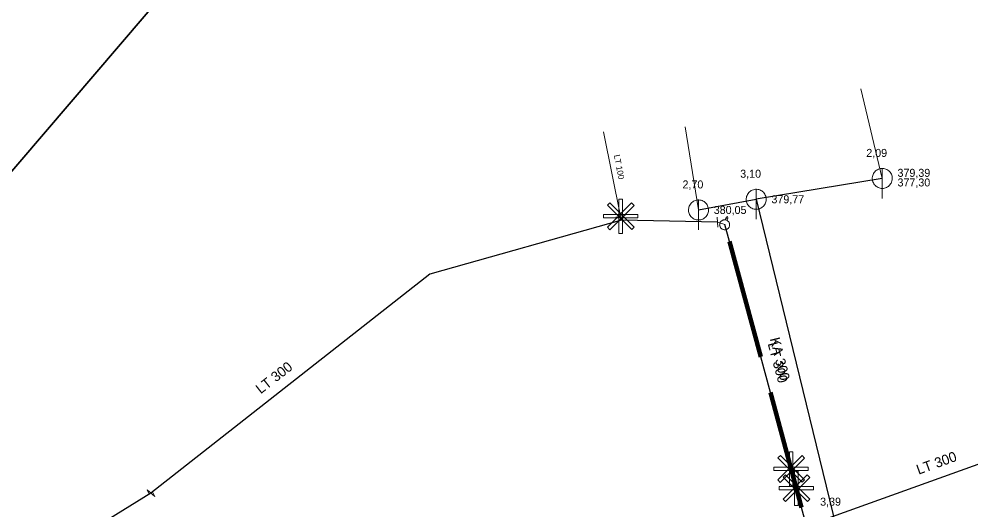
# Model space of a CAD drawing. Extents: x -809028 to -807737, y -990545 to -989489.
# Drawn here: x -807969.4 to -807874.2, y -989973.9 to -989924.8 of the extents above; entities that cross this region are included whole.
import ezdxf

# ---------------------------------------------------------------- set-up
doc = ezdxf.new("R2010")
doc.units = 0
doc.header["$LTSCALE"] = 0.32
for name, color, linetype, lineweight in [('1', 7, 'Continuous', 13), ('11', 7, 'Continuous', 13), ('12', 7, 'Continuous', 13), ('13', 7, 'Continuous', 13), ('14', 7, 'Continuous', 25), ('17', 7, 'Continuous', 25), ('22', 7, 'Continuous', 13), ('23', 7, 'Continuous', 13), ('3', 7, 'Continuous', 106), ('34', 7, 'Continuous', 13), ('47', 7, 'Continuous', 13)]:
    doc.layers.add(name, color=color, linetype=linetype, lineweight=lineweight)

msp = doc.modelspace()

# ---------------------------------------------------------------- linework, layer by layer
at = {"layer": '11'}
for p, q in [((-807885.249, -989931.787), (-807883.111, -989940.732)), ((-807902.817, -989935.557), (-807901.481, -989943.883))]:
    msp.add_line(p, q, dxfattribs=at)
at = {"layer": '12'}
for points in [[(-807908.166, -989943.181), (-807907.918, -989943.429), (-807910.347, -989945.858), (-807910.593, -989945.61)], [(-807910.585, -989943.42), (-807910.338, -989943.172), (-807907.909, -989945.601), (-807908.156, -989945.849)], [(-807909.432, -989942.817), (-807909.081, -989942.817), (-807909.081, -989946.252), (-807909.432, -989946.252)], [(-807907.548, -989944.326), (-807907.548, -989944.676), (-807910.983, -989944.676), (-807910.983, -989944.326)], [(-807891.129, -989968.44), (-807890.88, -989968.688), (-807893.309, -989971.117), (-807893.556, -989970.869)], [(-807893.548, -989968.679), (-807893.301, -989968.431), (-807890.872, -989970.86), (-807891.119, -989971.108)], [(-807892.395, -989968.076), (-807892.044, -989968.076), (-807892.044, -989971.511), (-807892.395, -989971.511)], [(-807890.511, -989969.585), (-807890.511, -989969.935), (-807893.946, -989969.935), (-807893.946, -989969.585)], [(-807891.873, -989970.008), (-807891.522, -989970.008), (-807891.522, -989973.443), (-807891.873, -989973.443)], [(-807890.607, -989970.372), (-807890.358, -989970.62), (-807892.788, -989973.049), (-807893.034, -989972.801)], [(-807893.026, -989970.611), (-807892.779, -989970.363), (-807890.35, -989972.792), (-807890.597, -989973.04)], [(-807889.989, -989971.517), (-807889.989, -989971.867), (-807893.424, -989971.867), (-807893.424, -989971.517)]]:
    msp.add_lwpolyline(points, close=True, dxfattribs=at)
at = {"layer": '13'}
msp.add_line((-807909.274, -989944.502), (-807910.972, -989936.071), dxfattribs=at)
at = {"layer": '14'}
for p, q in [((-807883.111, -989940.732), (-807895.714, -989942.814)), ((-807901.481, -989943.883), (-807895.714, -989942.814)), ((-807895.714, -989942.814), (-807887.723, -989975.604))]:
    msp.add_line(p, q, dxfattribs=at)
at = {"layer": '14', "lineweight": 13}
for p, q in [((-807909.183, -989944.896), (-807909.274, -989944.502)), ((-807899.582, -989945.1), (-807898.839, -989945.348))]:
    msp.add_line(p, q, dxfattribs=at)
at = {"layer": '17', "lineweight": 35}
msp.add_lwpolyline([(-808175.378, -990021.169), (-807992.059, -989965.616), (-807931.655, -989894.969), (-807887.769, -989859.528)], dxfattribs=at)
at = {"layer": '17'}
for points in [[(-807899.582, -989945.1), (-807909.183, -989944.896), (-807928.34, -989950.305), (-807956.229, -989972.189)], [(-807890.69, -989975.466), (-807891.197, -989973.625), (-807894.291, -989962.142), (-807895.239, -989958.565), (-807898.383, -989947.041), (-807898.839, -989945.348)], [(-807862.291, -989965.17), (-807871.427, -989968.552), (-807890.361, -989975.353)], [(-807956.229, -989972.189), (-807990.103, -989993.177), (-808009.471, -989995.802), (-808011.239, -989996.245)]]:
    msp.add_lwpolyline(points, dxfattribs=at)
at = {"layer": '22'}
for p, q in [((-807883.111, -989942.732), (-807883.11, -989939.732)), ((-807895.714, -989944.814), (-807895.713, -989941.814)), ((-807901.481, -989945.883), (-807901.48, -989942.883))]:
    msp.add_line(p, q, dxfattribs=at)
for points in [[(-807882.111, -989940.732), (-807882.116, -989940.623), (-807882.134, -989940.515), (-807882.164, -989940.409), (-807882.204, -989940.308), (-807882.256, -989940.211), (-807882.318, -989940.121), (-807882.39, -989940.038), (-807882.47, -989939.964), (-807882.558, -989939.898), (-807882.652, -989939.843), (-807882.752, -989939.798), (-807882.857, -989939.765), (-807882.964, -989939.743), (-807883.073, -989939.733), (-807883.183, -989939.735), (-807883.291, -989939.749), (-807883.398, -989939.774), (-807883.501, -989939.811), (-807883.599, -989939.86), (-807883.691, -989939.918), (-807883.777, -989939.987), (-807883.854, -989940.064), (-807883.923, -989940.15), (-807883.982, -989940.242), (-807884.03, -989940.34), (-807884.067, -989940.443), (-807884.093, -989940.55), (-807884.107, -989940.658), (-807884.11, -989940.768), (-807884.1, -989940.877), (-807884.079, -989940.984), (-807884.045, -989941.088), (-807884.001, -989941.188), (-807883.946, -989941.283), (-807883.88, -989941.371), (-807883.806, -989941.451), (-807883.723, -989941.523), (-807883.633, -989941.585), (-807883.537, -989941.637), (-807883.435, -989941.678), (-807883.33, -989941.708), (-807883.222, -989941.726), (-807883.112, -989941.732), (-807883.003, -989941.726), (-807882.895, -989941.708), (-807882.79, -989941.679), (-807882.688, -989941.638), (-807882.591, -989941.586), (-807882.501, -989941.524), (-807882.418, -989941.453), (-807882.343, -989941.373), (-807882.278, -989941.285), (-807882.222, -989941.191), (-807882.178, -989941.091), (-807882.144, -989940.987), (-807882.122, -989940.879), (-807882.112, -989940.77)], [(-807894.714, -989942.814), (-807894.719, -989942.705), (-807894.737, -989942.597), (-807894.767, -989942.491), (-807894.807, -989942.39), (-807894.859, -989942.293), (-807894.921, -989942.203), (-807894.993, -989942.12), (-807895.073, -989942.046), (-807895.161, -989941.98), (-807895.255, -989941.925), (-807895.355, -989941.88), (-807895.46, -989941.847), (-807895.567, -989941.825), (-807895.676, -989941.815), (-807895.786, -989941.817), (-807895.894, -989941.831), (-807896.001, -989941.856), (-807896.104, -989941.893), (-807896.202, -989941.942), (-807896.294, -989942), (-807896.38, -989942.069), (-807896.457, -989942.146), (-807896.526, -989942.232), (-807896.585, -989942.324), (-807896.633, -989942.422), (-807896.67, -989942.525), (-807896.696, -989942.632), (-807896.71, -989942.74), (-807896.713, -989942.85), (-807896.703, -989942.959), (-807896.682, -989943.066), (-807896.648, -989943.17), (-807896.604, -989943.27), (-807896.549, -989943.365), (-807896.483, -989943.453), (-807896.409, -989943.533), (-807896.326, -989943.605), (-807896.236, -989943.667), (-807896.14, -989943.719), (-807896.038, -989943.76), (-807895.933, -989943.79), (-807895.825, -989943.808), (-807895.715, -989943.814), (-807895.606, -989943.808), (-807895.498, -989943.79), (-807895.393, -989943.761), (-807895.291, -989943.72), (-807895.194, -989943.668), (-807895.104, -989943.606), (-807895.021, -989943.535), (-807894.946, -989943.455), (-807894.881, -989943.367), (-807894.825, -989943.273), (-807894.781, -989943.173), (-807894.747, -989943.069), (-807894.725, -989942.961), (-807894.715, -989942.852)], [(-807900.481, -989943.883), (-807900.486, -989943.774), (-807900.504, -989943.666), (-807900.534, -989943.56), (-807900.574, -989943.459), (-807900.626, -989943.362), (-807900.688, -989943.272), (-807900.76, -989943.189), (-807900.84, -989943.115), (-807900.928, -989943.049), (-807901.022, -989942.994), (-807901.122, -989942.949), (-807901.227, -989942.916), (-807901.334, -989942.894), (-807901.443, -989942.884), (-807901.553, -989942.886), (-807901.661, -989942.9), (-807901.768, -989942.925), (-807901.871, -989942.962), (-807901.969, -989943.011), (-807902.061, -989943.069), (-807902.147, -989943.138), (-807902.224, -989943.215), (-807902.293, -989943.301), (-807902.352, -989943.393), (-807902.4, -989943.491), (-807902.437, -989943.594), (-807902.463, -989943.701), (-807902.477, -989943.809), (-807902.48, -989943.919), (-807902.47, -989944.028), (-807902.449, -989944.135), (-807902.415, -989944.239), (-807902.371, -989944.339), (-807902.316, -989944.434), (-807902.25, -989944.522), (-807902.176, -989944.602), (-807902.093, -989944.674), (-807902.003, -989944.736), (-807901.907, -989944.788), (-807901.805, -989944.829), (-807901.7, -989944.859), (-807901.592, -989944.877), (-807901.482, -989944.883), (-807901.373, -989944.877), (-807901.265, -989944.859), (-807901.16, -989944.83), (-807901.058, -989944.789), (-807900.961, -989944.737), (-807900.871, -989944.675), (-807900.788, -989944.604), (-807900.713, -989944.524), (-807900.648, -989944.436), (-807900.592, -989944.342), (-807900.548, -989944.242), (-807900.514, -989944.138), (-807900.492, -989944.03), (-807900.482, -989943.921)]]:
    msp.add_lwpolyline(points, close=True, dxfattribs=at)
at = {"layer": '23'}
msp.add_line((-807898.553, -989944.76), (-807898.739, -989944.698), dxfattribs=at)
for points in [[(-807898.769, -989944.79), (-807898.722, -989944.649), (-807898.581, -989944.537), (-807898.536, -989944.711), (-807898.583, -989944.852)], [(-807898.391, -989945.515), (-807898.378, -989945.463), (-807898.37, -989945.411), (-807898.368, -989945.36), (-807898.371, -989945.308), (-807898.379, -989945.256), (-807898.394, -989945.205), (-807898.413, -989945.157), (-807898.436, -989945.111), (-807898.465, -989945.067), (-807898.498, -989945.026), (-807898.535, -989944.989), (-807898.576, -989944.956), (-807898.62, -989944.928), (-807898.666, -989944.905), (-807898.714, -989944.886), (-807898.767, -989944.872), (-807898.817, -989944.864), (-807898.871, -989944.862), (-807898.921, -989944.864), (-807898.973, -989944.872), (-807899.025, -989944.888), (-807899.073, -989944.906), (-807899.12, -989944.931), (-807899.164, -989944.958), (-807899.204, -989944.992), (-807899.241, -989945.03), (-807899.273, -989945.07), (-807899.301, -989945.114), (-807899.325, -989945.161), (-807899.344, -989945.209), (-807899.357, -989945.26), (-807899.365, -989945.312), (-807899.368, -989945.365), (-807899.365, -989945.416), (-807899.356, -989945.467), (-807899.342, -989945.518), (-807899.324, -989945.567), (-807899.299, -989945.614), (-807899.27, -989945.658)], [(-807898.871, -989944.862), (-807898.921, -989944.864), (-807898.973, -989944.872), (-807899.025, -989944.888), (-807899.073, -989944.906), (-807899.12, -989944.931), (-807899.164, -989944.958), (-807899.204, -989944.992), (-807899.241, -989945.03), (-807899.273, -989945.07), (-807899.301, -989945.114), (-807899.325, -989945.161), (-807899.344, -989945.209), (-807899.357, -989945.26), (-807899.365, -989945.312), (-807899.368, -989945.365), (-807899.365, -989945.416), (-807899.356, -989945.467), (-807899.342, -989945.518), (-807899.324, -989945.567), (-807899.299, -989945.614), (-807899.27, -989945.658), (-807899.238, -989945.698), (-807899.2, -989945.735), (-807899.161, -989945.768), (-807899.115, -989945.796), (-807899.069, -989945.818), (-807899.02, -989945.838), (-807898.97, -989945.85), (-807898.918, -989945.859), (-807898.865, -989945.862), (-807898.813, -989945.858), (-807898.761, -989945.85), (-807898.712, -989945.837), (-807898.663, -989945.817), (-807898.616, -989945.794), (-807898.573, -989945.765), (-807898.531, -989945.732), (-807898.494, -989945.694), (-807898.462, -989945.654)], [(-807899.27, -989945.658), (-807899.238, -989945.698), (-807899.2, -989945.735), (-807899.161, -989945.768), (-807899.115, -989945.796), (-807899.069, -989945.818), (-807899.02, -989945.838), (-807898.97, -989945.85), (-807898.918, -989945.859), (-807898.865, -989945.862), (-807898.813, -989945.858), (-807898.761, -989945.85), (-807898.712, -989945.837), (-807898.663, -989945.817), (-807898.616, -989945.794), (-807898.573, -989945.765), (-807898.531, -989945.732), (-807898.494, -989945.694), (-807898.462, -989945.654), (-807898.434, -989945.609), (-807898.411, -989945.563), (-807898.391, -989945.515), (-807898.378, -989945.463), (-807898.37, -989945.411), (-807898.368, -989945.36), (-807898.371, -989945.308), (-807898.379, -989945.256), (-807898.394, -989945.205), (-807898.413, -989945.157), (-807898.436, -989945.111), (-807898.465, -989945.067), (-807898.498, -989945.026), (-807898.535, -989944.989), (-807898.576, -989944.956), (-807898.62, -989944.928), (-807898.666, -989944.905), (-807898.714, -989944.886), (-807898.767, -989944.872), (-807898.817, -989944.864), (-807898.871, -989944.862)], [(-807898.462, -989945.654), (-807898.434, -989945.609), (-807898.411, -989945.563), (-807898.391, -989945.515)]]:
    msp.add_lwpolyline(points, dxfattribs=at)
at = {"layer": '3'}
for p, q in [((-807895.24, -989958.565), (-807898.383, -989947.042)), ((-807891.197, -989973.625), (-807894.291, -989962.142))]:
    msp.add_line(p, q, dxfattribs=at)
at = {"layer": '3', "lineweight": 100}
for p, q in [((-807895.24, -989958.565), (-807898.383, -989947.042)), ((-807891.197, -989973.625), (-807894.291, -989962.142))]:
    msp.add_line(p, q, dxfattribs=at)
at = {"layer": '34'}
for p, q in [((-807909.761, -989944.614), (-807908.786, -989944.39)), ((-807899.546, -989945.598), (-807899.616, -989944.601))]:
    msp.add_line(p, q, dxfattribs=at)
at = {"layer": '47'}
msp.add_line((-807956.614, -989971.856), (-807956.387, -989972.313), dxfattribs=at)
msp.add_lwpolyline([(-807956.614, -989971.856), (-807955.843, -989972.521), (-807956.07, -989972.064)], dxfattribs=at)

# ---------------------------------------------------------------- texts
at = {"layer": '1'}
for s, p in [('2,09', (-807884.711, -989938.58)), ('3,10', (-807897.314, -989940.662)), ('2,70', (-807903.081, -989941.731)), ('379,77', (-807894.192, -989943.214)), ('380,05', (-807899.959, -989944.283)), ('3,39', (-807889.323, -989973.452))]:
    msp.add_text(s, height=0.8, dxfattribs=at).set_placement(p)
for s, height, rotation, p in [('LT 100', 0.6, 281, (-807909.947, -989938.415)), ('KA 300', 1, 284, (-807894.358, -989956.764)), ('LT 300', 1, 285, (-807894.575, -989957.247)), ('LT 300', 1, 38, (-807945.253, -989962.323)), ('LT 300', 1, 20, (-807879.482, -989970.358))]:
    msp.add_text(s, height=height, rotation=rotation, dxfattribs=at).set_placement(p)
at = {"layer": '14'}
for s, p in [('379,39', (-807881.589, -989940.572)), ('377,30', (-807881.589, -989941.532))]:
    msp.add_text(s, height=0.8, dxfattribs=at).set_placement(p)

doc.saveas('drawing.dxf')
